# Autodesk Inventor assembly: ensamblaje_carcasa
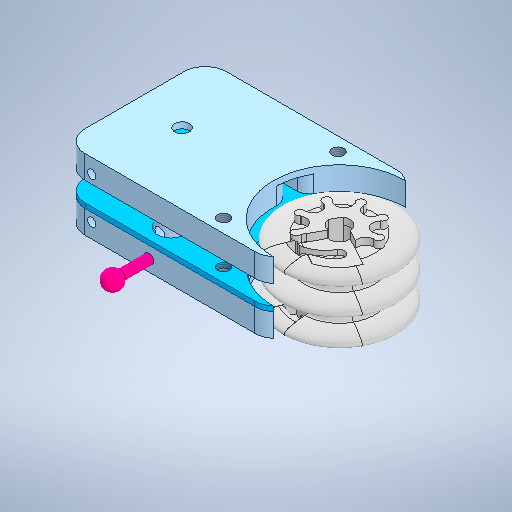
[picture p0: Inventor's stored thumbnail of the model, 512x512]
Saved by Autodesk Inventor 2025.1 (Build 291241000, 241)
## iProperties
Created: 2026-01
Part Number: ensamblaje_carcasa
Document SubType Name: Assembly
Designer: Usuario
Author: Usuario
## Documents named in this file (6)
- C:\Users\Usuario\Desktop\EXOGLOVE\actuacion\enclosure_poleas\ensamblaje_carcasa.iam
- C:\Users\Usuario\Desktop\EXOGLOVE\actuacion\enclosure_poleas\capa_2.ipt
- C:\Users\Usuario\Desktop\EXOGLOVE\actuacion\enclosure_poleas\capa1_capa3.ipt
- C:\Users\Usuario\Desktop\EXOGLOVE\actuacion\Dog_clutch\polea_metal.ipt
- C:\Users\Usuario\Desktop\EXOGLOVE\actuacion\Dog_clutch\spool_clutch_Enero26.ipt
- C:\Users\Usuario\Desktop\EXOGLOVE\actuacion\enclosure_poleas\seguro.ipt
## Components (6 placed, 5 different names)
1. capa_2:1 — Nivelación:1, Coincidencia:6, Coincidencia:7
2. capa1_capa3:1 — Nivelación:1, Coincidencia:2, Coincidencia:3, Coincidencia:4, Coincidencia:5, Coincidencia:6, Coincidencia:7, Coincidencia:8, Coincidencia:9, Coincidencia:10
3. polea_metal:1 — Coincidencia:4, Coincidencia:5
4. polea_metal:2 — Coincidencia:2, Coincidencia:3
5. spool_clutch_Enero26:1 — Coincidencia:8
6. seguro:1 — Coincidencia:9, Coincidencia:10
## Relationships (10: Mate 9, Flush 1)
- Nivelación:1 [Flush]: capa_2:1 ↔ capa1_capa3:1
- Coincidencia:2 [Mate]: capa1_capa3:1 ↔ polea_metal:2
- Coincidencia:3 [Mate]: capa1_capa3:1 ↔ polea_metal:2
- Coincidencia:4 [Mate]: capa1_capa3:1 ↔ polea_metal:1
- Coincidencia:5 [Mate]: capa1_capa3:1 ↔ polea_metal:1
- Coincidencia:6 [Mate]: capa_2:1 ↔ capa1_capa3:1
- Coincidencia:7 [Mate]: capa_2:1 ↔ capa1_capa3:1
- Coincidencia:8 [Mate]: capa1_capa3:1 ↔ spool_clutch_Enero26:1
- Coincidencia:9 [Mate]: capa1_capa3:1 ↔ seguro:1
- Coincidencia:10 [Mate]: capa1_capa3:1 ↔ seguro:1
